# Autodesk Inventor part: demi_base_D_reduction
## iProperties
Shininess: 64.0
Length Units: 11269
Angle Units: 11279
Time Units: 11290
Mass Units: 11283
Length Display Precision: 3
Angle Display Precision: 2
Compacted: True
Part Number: demi_base_D_reduction
Document SubType Name: Modeling
Created: 2008-02
Material: Acier doux
Designer: Pascal
Density: 0.0
Volumn: 0.0
Area: 0.0
PropertySet Name: Model Information
Control State: 0
Master: False
Checked Out: False
MATIERE_PIECE: X2CrNi 18-11
OBSERVATIONS: Tôle ep. 15/10
DESIGNATION: Demi-réduction droite
Author: Pascal
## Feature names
1. Lissage1
2. Coque1
3. Extrusion1
